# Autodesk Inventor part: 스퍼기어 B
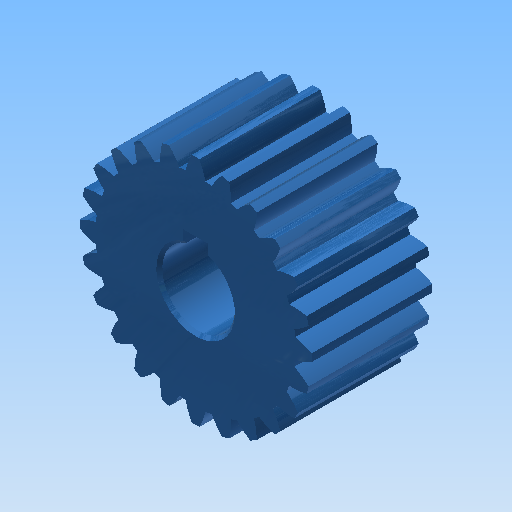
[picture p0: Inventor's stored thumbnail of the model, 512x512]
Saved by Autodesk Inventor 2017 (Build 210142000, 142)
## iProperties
Created: 2020-04
Part Number: 스퍼기어 B
Material: Steel
Document SubType Name: Modeling
Designer: mduedu
Categories: <?xml version="1.0" encoding="UTF-16"?> <MemberInstance><Categories><FamilyTemplate><FamilyTemplateParameter ValueType="xs:double" Id="1" ObjectReferenceKey="da
Density: 7.85 g/cm^3
Mass: 140.141 g
Surface Area: 65.0479 cm^2
Volume: 17.8523 cm^3
Appearance: 청록색
CustomPartVersion: 1
Author: mduedu
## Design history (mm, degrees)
sketch "Sketch1"
  geometry: C1 r 19.2 at (0, 0)
  constraints: 1 centre point
  dimensions: "d0" = 38.4 diameter of C1 (= da_da)
extrude "Extrusion1" new body sketch "Sketch1" distance "d1" = 20 (= da_b); taper "d2" = 0 deg
workplane "Work Plane2"
sketch "Sketch2"
  geometry: C1 r 19.2 at (0, 0) reference; C2 r 18 at (0, 0)
  constraints: 1 centre point, 1 coincident
  dimensions: "d3" = 36 diameter of C2 (= da_dw)
feature "피치 지름" sketch "Sketch2" dims "d4" = 10, "d5" = 0
workplane "Work Plane8"
workplane "Work Plane9"
feature "스퍼 기어" dims "da_b" = 20, "da_d" = 36, "da_aw" = 45, "da_da" = 38.4, "da_df" = 33.129, "da_dw" = 36, angle "da_beta" = 0 deg, "da_lefttooth" = 0, "da_righttooth" = 0
sketch "스케치3"
  geometry: L1 (-2, 5.657)-(2, 5.657); L2 (2, 5.657)-(2, 7.8); L3 (2, 7.8)-(-2, 7.8); L4 (-2, 7.8)-(-2, 5.657); A1 r 6 centre (0, 0) between (-2, 5.657) and (2, 5.657); 1 further point
  constraints: 8 end point, 2 parallel, 2 point on circle, 1 centre point, 1 coincident, 1 horizontal, 1 perpendicular
  dimensions: "d49" = 12 diameter of A1; "d51" = 4 distance of L2.end L3.end; "d52" = 13.8 dimension on A1 L3
extrude "돌출2" cut sketch "스케치3" stored distance "d53" = 10; taper "d54" = 0 deg
chamfer "모따기1" distance "d55" = 0.5; stored, may be unused: second distance "d56" = 2, angle "d57" = 45 deg
body "Solid1"
body "Srf1"
other parameters: "d16" = 45 (= da_aw), "d17" = 0, "d34" = 7.5 deg (computed from da_z), "d39" = 0, "d41" = 0, "d43" = 45 (= da_aw), "d46" = 45 (= da_aw), "d47" = 0, "d48" = 0
